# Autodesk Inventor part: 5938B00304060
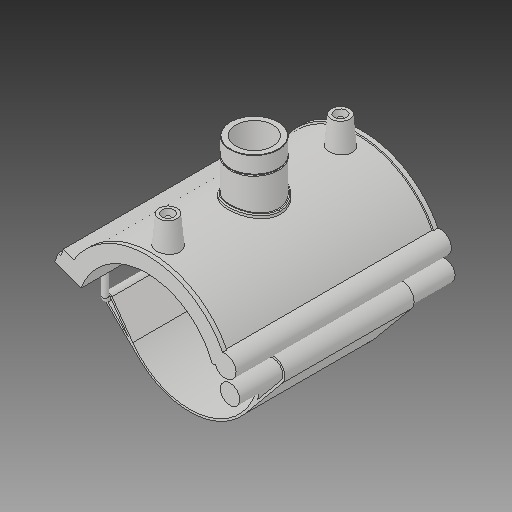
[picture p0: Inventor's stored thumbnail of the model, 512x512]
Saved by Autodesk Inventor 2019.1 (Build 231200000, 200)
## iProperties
Created: 2017-07
Part Number: 5938B00304060
Material: Generic
Description: PLASSON TRANSITION SADDLE 4''IPS x 1"NPT
Document SubType Name: Modeling
Designer: KIM
Density: 1 g/cm^3
Appearance: Default
Author: KIM
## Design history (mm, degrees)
derived "5938B.ipt"
feature "Solid1::5938B.ipt"
tag "TaggingFeature1"
body "Solid1"
other parameters: "d_" = 114.1, "B_" = 156.21, "H_" = 41.91, "L_" = 176.022, "d_t" = 6, "G_" = 30.291, "d148" = 1.7115, "d160" = 1.7115, "d169" = 1.7115, "d192" = 4.564, "d0" = 114.1, "d1" = 136.92, "d2" = 390.525, "d3" = 28.525, "d4" = 176.022, "d5" = 0, "d40" = 71.1984, "d41" = 42.4074, "d43" = 0, "d45" = 0, "d47" = 110.37, "d48" = 39.3783, "d50" = 0, "d78" = 90.46, "d79" = 15, "d80" = 70.4088, "d82" = 5 deg, "d84" = 4, "d85" = 14, "d86" = 0, "d87" = 3, "d88" = 0, "d96" = 139.6584, "d97" = 3.52044, "d98" = 0, "d102" = 0.90873, "d103" = 30.291, "d104" = 25.146, "d105" = 0, "d106" = 24.2328, "d108" = 0, "d109" = -13.97, "d111" = 0.5, "d112" = 0.5, "d113" = 0, "d114" = 0.5, "d117" = 0.30291, "d120" = 140 deg, "d121" = 24.228, "d122" = 20 deg, "d123" = 547.68, "d124" = 82.152, "d126" = 0, "d143" = 117.523, "d145" = 17.55385, "d149" = 1.7115, "d150" = 19.30923, "d153" = 176.022, "d154" = 0, "d156" = 68.46, "d157" = 160 deg, "d159" = 4.564, "d161" = 1.7115, "d162" = 105.6132, "d163" = 0, "d164" = 57.05, "d167" = 11.41, "d168" = 66.79024, "d170" = 1.7115, "d172" = 0, "d173" = 1, "d175" = 57.05, "d176" = 20 deg, "d177" = 7.987, "d178" = 22.82, "d180" = 0, "d183" = 9.128, "d184" = 6.3896, "d185" = 57.20715, "d186" = 57.20715, "d187" = 68.46, "d188" = 6.846, "d189" = 7.987, "d190" = 0, "d191" = 82.152, "d193" = 4.564, "d194" = 2.33905, "d195" = 90 deg, "d197" = 0, "d199" = 0
